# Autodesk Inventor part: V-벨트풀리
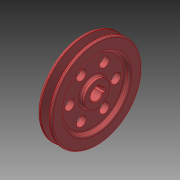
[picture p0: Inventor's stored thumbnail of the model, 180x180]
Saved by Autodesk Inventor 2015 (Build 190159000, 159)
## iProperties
Created: 2010-03
Part Number: V-벨트풀리
Document SubType Name: Modeling
Designer: Administrator
Density: 8 g/cm^3
Material: 스테인레스 스틸
Mass: 1147.33 g
Surface Area: 438.908 cm^2
Volume: 143.416 cm^3
Appearance: 기본값(2)
Author: Administrator
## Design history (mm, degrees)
sketch "스케치1"
  geometry: L1 (-10, 0)-(10, 0); L2 (10, 0)-(10, 65); L3 (-10, 65)-(-10, 0); L4 (10, 19)-(10, 0); L5 (-10, 65)-(-6.062, 65); L6 (-6.062, 65)-(-2.001, 52.5); L7 (2.001, 52.5)-(6.062, 65); L8 (6.062, 65)-(10, 65); L9 (-2.001, 52.5)-(2.001, 52.5); L10 (-10, 47)-(-4, 47); L11 (-4, 47)-(-4, 18); L12 (-4, 18)-(-10, 18); L13 (-10, 18)-(-10, 47); L14 (10, 47)-(4, 47); L15 (4, 47)-(4, 18); L16 (4, 18)-(10, 18); L17 (10, 18)-(10, 47); 5 further points
  constraints: 34 end point, 6 collinear, 6 horizontal, 5 parallel, 4 point on line, 3 perpendicular, 2 midpoint, 1 coincident, 1 horizontal alignment, 1 vertical alignment
  dimensions: "d0" = 121 diameter of point (-4.6, 60.5) L1; "d1" = 4.5 distance from line of L5 point (-4.6, 60.5); "d2" = 8 distance from line of L9 point (-4.6, 60.5); "d3" = 9.2 distance of point (-4.6, 60.5) point (4.6, 60.5); "d4" = 36 deg angle of L7 L6; "d5" = 10 distance from line of point (0, 52.5) L3; "d8" = 6 distance of L14.start L14.end; "d10" = 29 distance of L14.end L15.end; "d29" = 36 diameter of L16 L1
revolve "회전1" sketch "스케치1" stored, may be unused: angle "d11" = 90 deg
fillet "모깎기1" dims "d12" = 2, "d13" = 1, "d14" = 0.5
fillet "모깎기2" dims "d15" = 3
sketch "스케치2"
  geometry: L1 (-3, 8.485)-(3, 8.485); L2 (3, 8.485)-(3, 11.8); L3 (3, 11.8)-(-3, 11.8); L4 (-3, 11.8)-(-3, 8.485); C1 r 18 at (0, 0) reference; A1 r 9 centre (0, 0) between (-3, 8.485) and (3, 8.485)
  constraints: 8 end point, 2 parallel, 2 point on circle, 1 centre point, 1 concentric, 1 horizontal, 1 perpendicular
  dimensions: "d16" = 18 diameter of A1; "d19" = 2.8 distance edge to line of A1 L3; "d20" = 6 distance of L2.end L3.end
extrude "돌출1" cut sketch "스케치2" stored distance "d17" = 10; taper "d18" = 0 deg
chamfer "모따기1" distance "d30" = 1; stored, may be unused: second distance "d31" = 2, angle "d32" = 45 deg
sketch "스케치4" dims "d33" = 66
  geometry: C1 r 7 at (0, 33); 2 further points
  constraints: 2 vertical alignment, 1 centre point, 1 coincident, 2 other
  dimensions: "d34" = 14 diameter of C1
extrude "돌출2" cut sketch "스케치4" stored distance "d35" = 10; taper "d36" = 0 deg
node "솔리드1"
pattern_circular "원형 패턴1" dims angle "d38" = 360 deg
